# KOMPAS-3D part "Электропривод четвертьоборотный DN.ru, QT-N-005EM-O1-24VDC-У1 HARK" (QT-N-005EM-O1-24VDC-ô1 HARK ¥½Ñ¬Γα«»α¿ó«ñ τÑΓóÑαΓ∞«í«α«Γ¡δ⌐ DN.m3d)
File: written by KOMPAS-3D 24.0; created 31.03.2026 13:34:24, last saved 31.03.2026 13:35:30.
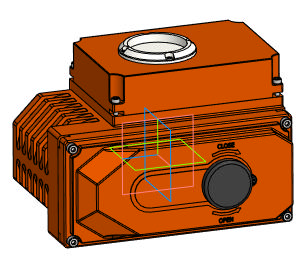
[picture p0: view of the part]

Document properties: Автор: DN.RU; Полное имя файла: D:\PROJECT CAD\DN.RU\...195\Исходники\24В\QT-N-005EM-O1-24VDC-У1 HARK Электропривод четвертьоборотный DN.ru\QT-N-005EM-O1-24VDC-У1 HARK Электропривод четвертьоборотный DN.m3d

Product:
- Body: Твердое тело1  | qty 1
    Масса: 13.496569
- Part/product: Электропривод четвертьоборотный DN.ru  | designation QT-N-005EM-O1-24VDC-У1 HARK
    Масса: 3.6
    Раздел спецификации: Прочие изделия
    Комментарий: D300-14478
    Примечание: D300-14479
    additional columns: Сталь

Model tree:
1. Твердое тело1  (labels: Твердое тело1)

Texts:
  QT-N-005EM-O1-24VDC-У1 HARK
